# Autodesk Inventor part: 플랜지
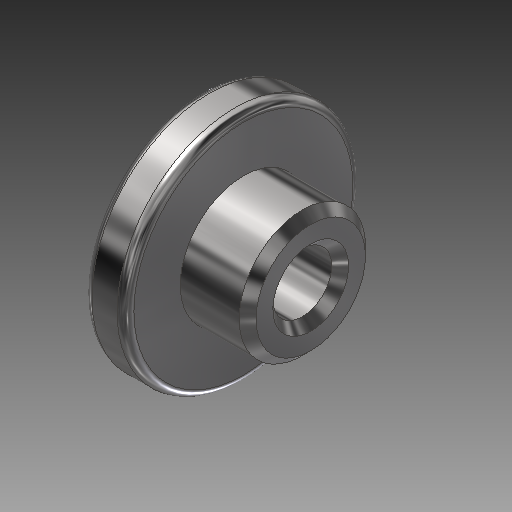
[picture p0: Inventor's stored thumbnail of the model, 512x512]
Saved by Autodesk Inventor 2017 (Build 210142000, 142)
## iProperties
Created: 2018-01
Part Number: 플랜지
Material: 스테인리스강
Document SubType Name: Modeling
Designer: mduedu
Density: 8.08 g/cm^3
Mass: 3.95967 g
Surface Area: 5.35087 cm^2
Volume: 0.490059 cm^3
Appearance: 반광택
Author: mduedu
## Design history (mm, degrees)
sketch "스케치1"
  geometry: L1 (0, 0)-(0, 7); L2 (0, 7)-(2.5, 7); L3 (2.5, 7)-(2.5, 3.75); L4 (2.5, 3.75)-(6.5, 3.75); L5 (6.5, 3.75)-(6.5, 0); L6 (6.5, 0)-(0, 0)
  constraints: 12 end point, 4 parallel, 1 perpendicular, 1 vertical
  dimensions: "d0" = 14 diameter of L2 L6; "d2" = 7.5 diameter of L4 L6; "d3" = 2.5 distance of L1.end L2.end; "d4" = 6.5 distance between parallel lines of L5 L1
revolve "회전1" sketch "스케치1" stored, may be unused: angle "d5" = 90 deg
hole "구멍1" diameter "d8" = 3.5; stored, may be unused: countersink angle "d12" = 90 deg, drill point angle "d14" = 118 deg; dims "d9" = 6, "d10" = 4, "d11" = 2, "d13" = 8, "d19" = 10, "d20" = 10
fillet "모깎기1" dims "d15" = 0.5
chamfer "모따기1" distance "d16" = 0.5; stored, may be unused: second distance "d17" = 2, angle "d18" = 45 deg
chamfer "모따기2" distance "d21" = 0.5; stored, may be unused: second distance "d22" = 2, angle "d23" = 45 deg
node "솔리드1"
